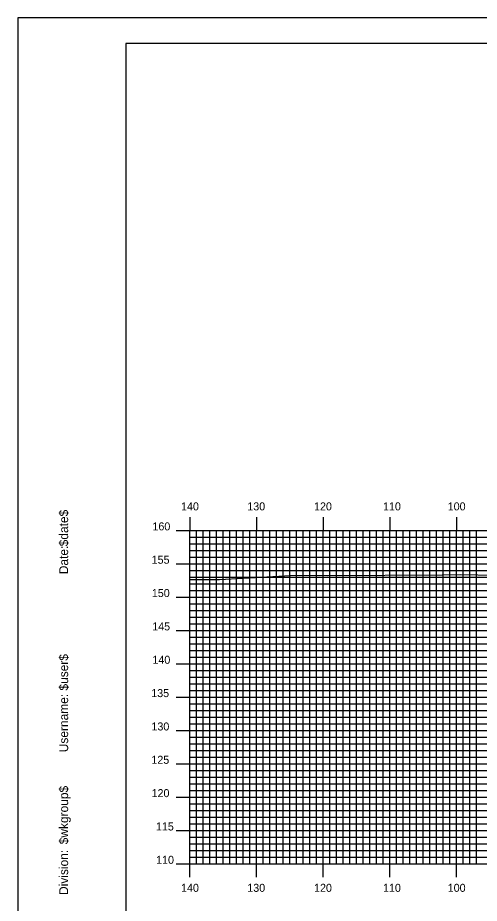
# Model space of a CAD drawing. Extents: x 1770055 to 1770398, y 442591 to 442811.
# Drawn here: x 1770054.7 to 1770123.9, y 442677.8 to 442810.5 of the extents above; entities that cross this region are included whole.
import ezdxf

# ---------------------------------------------------------------- set-up
doc = ezdxf.new("R2010")
doc.units = 0
for name, color, linetype in [('BORDER', 7, 'Continuous'), ('H_V ANNOTATION', 7, 'Continuous'), ('MAJOR', 7, 'Continuous'), ('MINOR', 7, 'Continuous'), ('PLOT BOUNDARY', 7, 'Continuous'), ('S_Roadway_Centerline', 7, 'Continuous')]:
    doc.layers.add(name, color=color, linetype=linetype)

msp = doc.modelspace()

# ---------------------------------------------------------------- linework, layer by layer
at = {"layer": 'BORDER'}
msp.add_lwpolyline([(1770070.93, 442596.67), (1770390.93, 442596.67), (1770390.93, 442806.67), (1770070.93, 442806.67)], close=True, dxfattribs=at)
at = {"layer": 'MAJOR'}
for p, q in [((1770080.53, 442735.67), (1770080.53, 442733.67)), ((1770090.53, 442735.67), (1770090.53, 442733.67)), ((1770100.53, 442735.67), (1770100.53, 442733.67)), ((1770110.53, 442735.67), (1770110.53, 442733.67)), ((1770120.53, 442735.67), (1770120.53, 442733.67)), ((1770078.52, 442733.67), (1770080.53, 442733.67)), ((1770080.53, 442733.67), (1770360.53, 442733.67)), ((1770080.53, 442683.67), (1770080.53, 442733.67)), ((1770080.53, 442683.67), (1770080.53, 442733.67)), ((1770080.53, 442733.67), (1770360.53, 442733.67)), ((1770090.53, 442683.67), (1770090.53, 442733.67)), ((1770100.53, 442683.67), (1770100.53, 442733.67)), ((1770110.53, 442683.67), (1770110.53, 442733.67)), ((1770120.53, 442683.67), (1770120.53, 442733.67)), ((1770078.52, 442728.67), (1770080.53, 442728.67)), ((1770080.53, 442728.67), (1770360.53, 442728.67)), ((1770078.52, 442723.67), (1770080.53, 442723.67)), ((1770080.53, 442723.67), (1770360.53, 442723.67)), ((1770078.52, 442718.67), (1770080.53, 442718.67)), ((1770080.53, 442718.67), (1770360.53, 442718.67)), ((1770078.52, 442713.67), (1770080.53, 442713.67)), ((1770080.53, 442713.67), (1770360.53, 442713.67)), ((1770078.52, 442708.67), (1770080.53, 442708.67)), ((1770080.53, 442708.67), (1770360.53, 442708.67)), ((1770078.52, 442703.67), (1770080.53, 442703.67)), ((1770080.53, 442703.67), (1770360.53, 442703.67)), ((1770078.52, 442698.67), (1770080.53, 442698.67)), ((1770080.53, 442698.67), (1770360.53, 442698.67)), ((1770078.52, 442693.67), (1770080.53, 442693.67)), ((1770080.53, 442693.67), (1770360.53, 442693.67)), ((1770078.52, 442688.67), (1770080.53, 442688.67)), ((1770080.53, 442688.67), (1770360.53, 442688.67)), ((1770078.52, 442683.67), (1770080.53, 442683.67)), ((1770080.53, 442683.67), (1770360.53, 442683.67)), ((1770080.53, 442683.67), (1770360.53, 442683.67)), ((1770080.53, 442681.66), (1770080.53, 442683.67)), ((1770090.53, 442681.66), (1770090.53, 442683.67)), ((1770100.53, 442681.66), (1770100.53, 442683.67)), ((1770110.53, 442681.66), (1770110.53, 442683.67)), ((1770120.53, 442681.66), (1770120.53, 442683.67))]:
    msp.add_line(p, q, dxfattribs=at)
at = {"layer": 'MINOR'}
for p, q in [((1770080.53, 442732.67), (1770360.53, 442732.67)), ((1770080.53, 442732.67), (1770082.53, 442732.67)), ((1770081.53, 442683.67), (1770081.53, 442733.67)), ((1770082.53, 442683.67), (1770082.53, 442733.67)), ((1770083.53, 442683.67), (1770083.53, 442733.67)), ((1770084.53, 442683.67), (1770084.53, 442733.67)), ((1770085.53, 442683.67), (1770085.53, 442733.67)), ((1770086.53, 442683.67), (1770086.53, 442733.67)), ((1770087.53, 442683.67), (1770087.53, 442733.67)), ((1770088.53, 442683.67), (1770088.53, 442733.67)), ((1770089.53, 442683.67), (1770089.53, 442733.67)), ((1770091.53, 442683.67), (1770091.53, 442733.67)), ((1770092.53, 442683.67), (1770092.53, 442733.67)), ((1770093.53, 442683.67), (1770093.53, 442733.67)), ((1770094.53, 442683.67), (1770094.53, 442733.67)), ((1770095.53, 442683.67), (1770095.53, 442733.67)), ((1770096.53, 442683.67), (1770096.53, 442733.67)), ((1770097.53, 442683.67), (1770097.53, 442733.67)), ((1770098.53, 442683.67), (1770098.53, 442733.67)), ((1770099.53, 442683.67), (1770099.53, 442733.67)), ((1770101.53, 442683.67), (1770101.53, 442733.67)), ((1770102.53, 442683.67), (1770102.53, 442733.67)), ((1770103.53, 442683.67), (1770103.53, 442733.67)), ((1770104.53, 442683.67), (1770104.53, 442733.67)), ((1770105.53, 442683.67), (1770105.53, 442733.67)), ((1770106.53, 442683.67), (1770106.53, 442733.67)), ((1770107.53, 442683.67), (1770107.53, 442733.67)), ((1770108.53, 442683.67), (1770108.53, 442733.67)), ((1770109.53, 442683.67), (1770109.53, 442733.67)), ((1770111.53, 442683.67), (1770111.53, 442733.67)), ((1770112.53, 442683.67), (1770112.53, 442733.67)), ((1770113.53, 442683.67), (1770113.53, 442733.67)), ((1770114.53, 442683.67), (1770114.53, 442733.67)), ((1770115.53, 442683.67), (1770115.53, 442733.67)), ((1770116.53, 442683.67), (1770116.53, 442733.67)), ((1770117.53, 442683.67), (1770117.53, 442733.67)), ((1770118.53, 442683.67), (1770118.53, 442733.67)), ((1770119.53, 442683.67), (1770119.53, 442733.67)), ((1770121.53, 442683.67), (1770121.53, 442733.67)), ((1770122.53, 442683.67), (1770122.53, 442733.67)), ((1770123.53, 442683.67), (1770123.53, 442733.67)), ((1770080.53, 442731.67), (1770360.53, 442731.67)), ((1770080.53, 442731.67), (1770082.53, 442731.67)), ((1770080.53, 442730.67), (1770360.53, 442730.67)), ((1770080.53, 442730.67), (1770082.53, 442730.67)), ((1770080.53, 442729.67), (1770360.53, 442729.67)), ((1770080.53, 442729.67), (1770082.53, 442729.67)), ((1770080.53, 442727.67), (1770360.53, 442727.67)), ((1770080.53, 442727.67), (1770082.53, 442727.67)), ((1770080.53, 442726.67), (1770360.53, 442726.67)), ((1770080.53, 442726.67), (1770082.53, 442726.67)), ((1770080.53, 442725.67), (1770360.53, 442725.67)), ((1770080.53, 442725.67), (1770082.53, 442725.67)), ((1770080.53, 442724.67), (1770360.53, 442724.67)), ((1770080.53, 442724.67), (1770082.53, 442724.67)), ((1770080.53, 442722.67), (1770360.53, 442722.67)), ((1770080.53, 442722.67), (1770082.53, 442722.67)), ((1770080.53, 442721.67), (1770360.53, 442721.67)), ((1770080.53, 442721.67), (1770082.53, 442721.67)), ((1770080.53, 442720.67), (1770360.53, 442720.67)), ((1770080.53, 442720.67), (1770082.53, 442720.67)), ((1770080.53, 442719.67), (1770360.53, 442719.67)), ((1770080.53, 442719.67), (1770082.53, 442719.67)), ((1770080.53, 442717.67), (1770360.53, 442717.67)), ((1770080.53, 442717.67), (1770082.53, 442717.67)), ((1770080.53, 442716.67), (1770360.53, 442716.67)), ((1770080.53, 442716.67), (1770082.53, 442716.67)), ((1770080.53, 442715.67), (1770360.53, 442715.67)), ((1770080.53, 442715.67), (1770082.53, 442715.67)), ((1770080.53, 442714.67), (1770360.53, 442714.67)), ((1770080.53, 442714.67), (1770082.53, 442714.67)), ((1770080.53, 442712.67), (1770360.53, 442712.67)), ((1770080.53, 442712.67), (1770082.53, 442712.67)), ((1770080.53, 442711.67), (1770360.53, 442711.67)), ((1770080.53, 442711.67), (1770082.53, 442711.67)), ((1770080.53, 442710.67), (1770360.53, 442710.67)), ((1770080.53, 442710.67), (1770082.53, 442710.67)), ((1770080.53, 442709.67), (1770360.53, 442709.67)), ((1770080.53, 442709.67), (1770082.53, 442709.67)), ((1770080.53, 442707.67), (1770360.53, 442707.67)), ((1770080.53, 442707.67), (1770082.53, 442707.67)), ((1770080.53, 442706.67), (1770360.53, 442706.67)), ((1770080.53, 442706.67), (1770082.53, 442706.67)), ((1770080.53, 442705.67), (1770360.53, 442705.67)), ((1770080.53, 442705.67), (1770082.53, 442705.67)), ((1770080.53, 442704.67), (1770360.53, 442704.67)), ((1770080.53, 442704.67), (1770082.53, 442704.67)), ((1770080.53, 442702.67), (1770360.53, 442702.67)), ((1770080.53, 442702.67), (1770082.53, 442702.67)), ((1770080.53, 442701.67), (1770360.53, 442701.67)), ((1770080.53, 442701.67), (1770082.53, 442701.67)), ((1770080.53, 442700.67), (1770360.53, 442700.67)), ((1770080.53, 442700.67), (1770082.53, 442700.67)), ((1770080.53, 442699.67), (1770360.53, 442699.67)), ((1770080.53, 442699.67), (1770082.53, 442699.67)), ((1770080.53, 442697.67), (1770360.53, 442697.67)), ((1770080.53, 442697.67), (1770082.53, 442697.67)), ((1770080.53, 442696.67), (1770360.53, 442696.67)), ((1770080.53, 442696.67), (1770082.53, 442696.67)), ((1770080.53, 442695.67), (1770360.53, 442695.67)), ((1770080.53, 442695.67), (1770082.53, 442695.67)), ((1770080.53, 442694.67), (1770360.53, 442694.67)), ((1770080.53, 442694.67), (1770082.53, 442694.67)), ((1770080.53, 442692.67), (1770360.53, 442692.67)), ((1770080.53, 442692.67), (1770082.53, 442692.67)), ((1770080.53, 442691.67), (1770360.53, 442691.67)), ((1770080.53, 442691.67), (1770082.53, 442691.67)), ((1770080.53, 442690.67), (1770360.53, 442690.67)), ((1770080.53, 442690.67), (1770082.53, 442690.67)), ((1770080.53, 442689.67), (1770360.53, 442689.67)), ((1770080.53, 442689.67), (1770082.53, 442689.67)), ((1770080.53, 442687.67), (1770360.53, 442687.67)), ((1770080.53, 442687.67), (1770082.53, 442687.67)), ((1770080.53, 442686.67), (1770360.53, 442686.67)), ((1770080.53, 442686.67), (1770082.53, 442686.67)), ((1770080.53, 442685.67), (1770360.53, 442685.67)), ((1770080.53, 442685.67), (1770082.53, 442685.67)), ((1770080.53, 442684.67), (1770360.53, 442684.67)), ((1770080.53, 442684.67), (1770082.53, 442684.67))]:
    msp.add_line(p, q, dxfattribs=at)
at = {"layer": 'PLOT BOUNDARY'}
msp.add_lwpolyline([(1770054.74, 442590.55), (1770394.74, 442590.55), (1770394.74, 442810.55), (1770054.74, 442810.55)], close=True, dxfattribs=at)
at = {"layer": 'S_Roadway_Centerline'}
msp.add_lwpolyline([(1770080.53, 442726.32), (1770082.81, 442726.32), (1770084.98, 442726.31), (1770088.52, 442726.5), (1770096.55, 442726.95), (1770101.23, 442726.89), (1770118.36, 442727.01), (1770121.05, 442727.06), (1770126.39, 442726.97)], dxfattribs=at)

# ---------------------------------------------------------------- texts
at = {"layer": 'BORDER'}
for s, p in [('$date$', (1770062.3, 442731.28)), ('Date:', (1770062.3, 442727.1)), ('$user$', (1770062.3, 442709.65)), ('Username:', (1770062.3, 442700.4)), ('$wkgroup$', (1770062.3, 442686.6)), ('Division:', (1770062.3, 442679))]:
    msp.add_text(s, height=1.339, rotation=90, dxfattribs=at).set_placement(p)
at = {"layer": 'H_V ANNOTATION'}
for s, p in [('140', (1770079.23, 442736.67)), ('130', (1770089.16, 442736.67)), ('120', (1770099.17, 442736.67)), ('110', (1770109.51, 442736.67)), ('100', (1770119.21, 442736.67)), ('160', (1770074.94, 442733.67)), ('155', (1770074.82, 442728.67)), ('150', (1770074.85, 442723.67)), ('145', (1770074.91, 442718.67)), ('140', (1770074.94, 442713.67)), ('135', (1770074.76, 442708.67)), ('130', (1770074.79, 442703.67)), ('125', (1770074.78, 442698.67)), ('120', (1770074.81, 442693.67)), ('115', (1770075.46, 442688.67)), ('110', (1770075.49, 442683.67)), ('140', (1770079.23, 442679.47)), ('130', (1770089.16, 442679.47)), ('120', (1770099.17, 442679.47)), ('110', (1770109.51, 442679.47)), ('100', (1770119.21, 442679.47))]:
    msp.add_text(s, height=1.2, dxfattribs=at).set_placement(p)
at = {"layer": 'MAJOR'}
msp.add_text('-', height=0.012, dxfattribs=at).set_placement((1770080.52, 442683.67))

doc.saveas('drawing.dxf')
